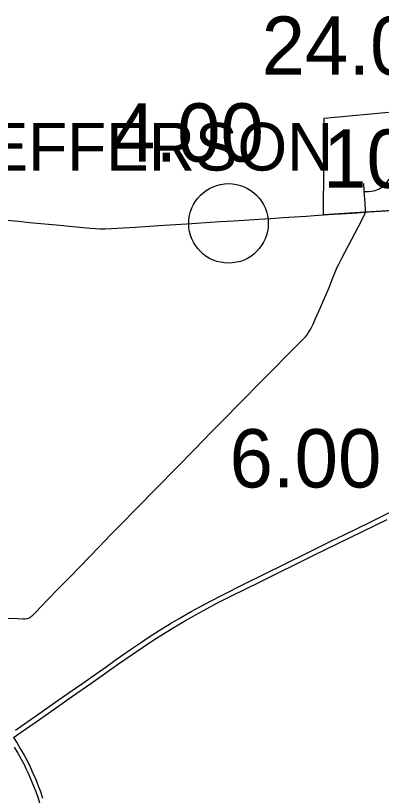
# Model space of a CAD drawing. Extents: x 1597222 to 1925846, y 496284 to 911751.
# Drawn here: x 1658757 to 1665653, y 592215 to 606923 of the extents above; entities that cross this region are included whole.
import ezdxf

# ---------------------------------------------------------------- set-up
doc = ezdxf.new("R2010")
doc.units = 0
for name, color, linetype in [('Default', 7, 'Continuous'), ('GM_X_City_Street', 7, 'Continuous'), ('GM_X_Corporation', 7, 'Continuous'), ('GM_X_County_Road', 7, 'Continuous'), ('GM_X_Interstate_Route', 7, 'Continuous'), ('GM_X_State_Route', 7, 'Continuous'), ('GM_X_Township_Text', 7, 'Continuous'), ('GM_X_US_Route', 7, 'Continuous')]:
    doc.layers.add(name, color=color, linetype=linetype)

msp = doc.modelspace()

# ---------------------------------------------------------------- linework, layer by layer
at = {"layer": 'Default'}
msp.add_circle((1662771, 603004), 750, dxfattribs=at)
msp.add_circle((1662771, 603004), 750, dxfattribs=at)
at = {"layer": 'GM_X_City_Street'}
for points in [[(1665330, 603602), (1665328, 603626), (1665321, 603755)], [(1665330, 603602), (1665359, 603603), (1665408, 603604), (1665458, 603609), (1665506, 603617), (1665538, 603625), (1665569, 603637), (1665600, 603650), (1665629, 603665), (1665657, 603683), (1665683, 603703), (1665708, 603724), (1665730, 603746), (1665744, 603763), (1665752, 603774), (1665799, 603835)], [(1665354, 603215), (1665351, 603270), (1665339, 603464), (1665330, 603602)]]:
    msp.add_lwpolyline(points, dxfattribs=at)
at = {"layer": 'GM_X_Corporation'}
msp.add_lwpolyline([(1665960, 603252), (1665349, 603213), (1664559, 603163), (1664571, 604990), (1665925, 605111)], dxfattribs=at)
at = {"layer": 'GM_X_County_Road'}
msp.add_lwpolyline([(1658523, 595560), (1658802, 595549), (1658900, 595546), (1658934, 595546), (1658967, 595550), (1658983, 595554), (1658999, 595559), (1659014, 595566), (1659029, 595573), (1659056, 595593), (1659069, 595604), (1659093, 595627), (1659138, 595674), (1659342, 595887), (1659583, 596134), (1659777, 596334), (1660154, 596722), (1660326, 596899), (1660554, 597134), (1660771, 597357), (1661012, 597603), (1661438, 598036), (1661771, 598375), (1662150, 598761), (1662276, 598891), (1662459, 599078), (1662573, 599196), (1662700, 599325), (1662964, 599594), (1663113, 599746), (1663275, 599909), (1663506, 600141), (1663622, 600258), (1663691, 600328), (1663783, 600421), (1663909, 600550), (1664059, 600701), (1664163, 600806), (1664219, 600866), (1664251, 600904), (1664280, 600944), (1664306, 600986), (1664330, 601029), (1664366, 601103), (1664412, 601208), (1664504, 601419), (1664665, 601796), (1664726, 601948), (1664781, 602085), (1664820, 602175), (1664848, 602234), (1664893, 602322), (1664968, 602467), (1665219, 602947), (1665333, 603165), (1665354, 603215)], dxfattribs=at)
at = {"layer": 'GM_X_Interstate_Route'}
for points in [[(1658753, 593445), (1658927, 593564), (1659257, 593798), (1659560, 594010), (1659904, 594252), (1660022, 594332), (1660255, 594497), (1660463, 594642), (1660637, 594764), (1660921, 594964), (1661110, 595092), (1661277, 595204), (1661465, 595325), (1661677, 595455), (1661840, 595552), (1662065, 595684), (1662240, 595779), (1662444, 595888), (1662663, 596001), (1663060, 596198), (1663840, 596584), (1664220, 596772), (1664534, 596927), (1664636, 596977), (1664726, 597022), (1664939, 597124), (1665439, 597370), (1665631, 597466), (1665996, 597645)], [(1658716, 593305), (1658907, 593440), (1659144, 593605), (1659378, 593767), (1659829, 594084), (1660178, 594327), (1660700, 594694), (1660955, 594873), (1661147, 595005), (1661363, 595148), (1661546, 595264), (1661758, 595395), (1661959, 595513), (1662176, 595636), (1662369, 595742), (1662566, 595846), (1662815, 595971), (1663365, 596243), (1664380, 596744), (1665760, 597422)]]:
    msp.add_lwpolyline(points, dxfattribs=at)
at = {"layer": 'GM_X_State_Route'}
for points in [[(1664747, 603176), (1664876, 603184), (1665106, 603199), (1665354, 603215), (1665417, 603219), (1665744, 603241), (1666055, 603260), (1666268, 603274), (1666530, 603290), (1666940, 603317), (1667000, 603321), (1667087, 603327), (1667284, 603339), (1667415, 603347), (1667693, 603365), (1667795, 603371), (1667857, 603375), (1668004, 603384), (1668135, 603391), (1668184, 603396), (1668216, 603401), (1668231, 603406), (1668256, 603414)], [(1658596, 603062), (1658809, 603043), (1659021, 603023), (1659593, 602970), (1659838, 602945), (1660164, 602914), (1660262, 602907), (1660344, 602904), (1660442, 602903), (1660557, 602907), (1660786, 602920), (1661016, 602935), (1661458, 602963), (1661769, 602982), (1662080, 603003), (1662424, 603025), (1662620, 603037), (1662866, 603053), (1663161, 603070), (1663341, 603081), (1663570, 603098), (1663799, 603112), (1664012, 603126), (1664241, 603142), (1664388, 603152), (1664562, 603165)], [(1664562, 603165), (1664653, 603171), (1664747, 603176)]]:
    msp.add_lwpolyline(points, dxfattribs=at)
at = {"layer": 'GM_X_US_Route'}
for points in [[(1658716, 593305), (1658784, 593199), (1658852, 593087), (1658918, 592973), (1658979, 592858), (1659030, 592755), (1659085, 592636), (1659136, 592515), (1659185, 592394), (1659225, 592286), (1659266, 592162)], [(1658732, 593127), (1658799, 593014), (1658863, 592900), (1658917, 592798), (1658953, 592724), (1658995, 592635), (1659041, 592530), (1659091, 592408), (1659138, 592286), (1659181, 592161), (1659215, 592052), (1659250, 591925), (1659282, 591798), (1659307, 591686), (1659330, 591573), (1659351, 591443), (1659372, 591297), (1659417, 590939), (1659456, 590630), (1659493, 590337), (1659533, 590028), (1659545, 589947), (1659556, 589879)]]:
    msp.add_lwpolyline(points, dxfattribs=at)

# ---------------------------------------------------------------- texts
at = {"layer": 'Default'}
for s, p in [('24.00', (1663395, 605806)), ('24.00', (1663395, 605806)), ('4.00', (1660575, 604168)), ('4.00', (1660575, 604168)), ('10.15', (1664555, 603675)), ('10.15', (1664555, 603675)), ('6.00', (1662790, 598023)), ('6.00', (1662790, 598023))]:
    msp.add_text(s, height=1100, dxfattribs=at).set_placement(p)
at = {"layer": 'GM_X_Township_Text'}
msp.add_text('JEFFERSON', height=900, rotation=0, dxfattribs=at).set_placement((1657590, 604000))

doc.saveas('drawing.dxf')
